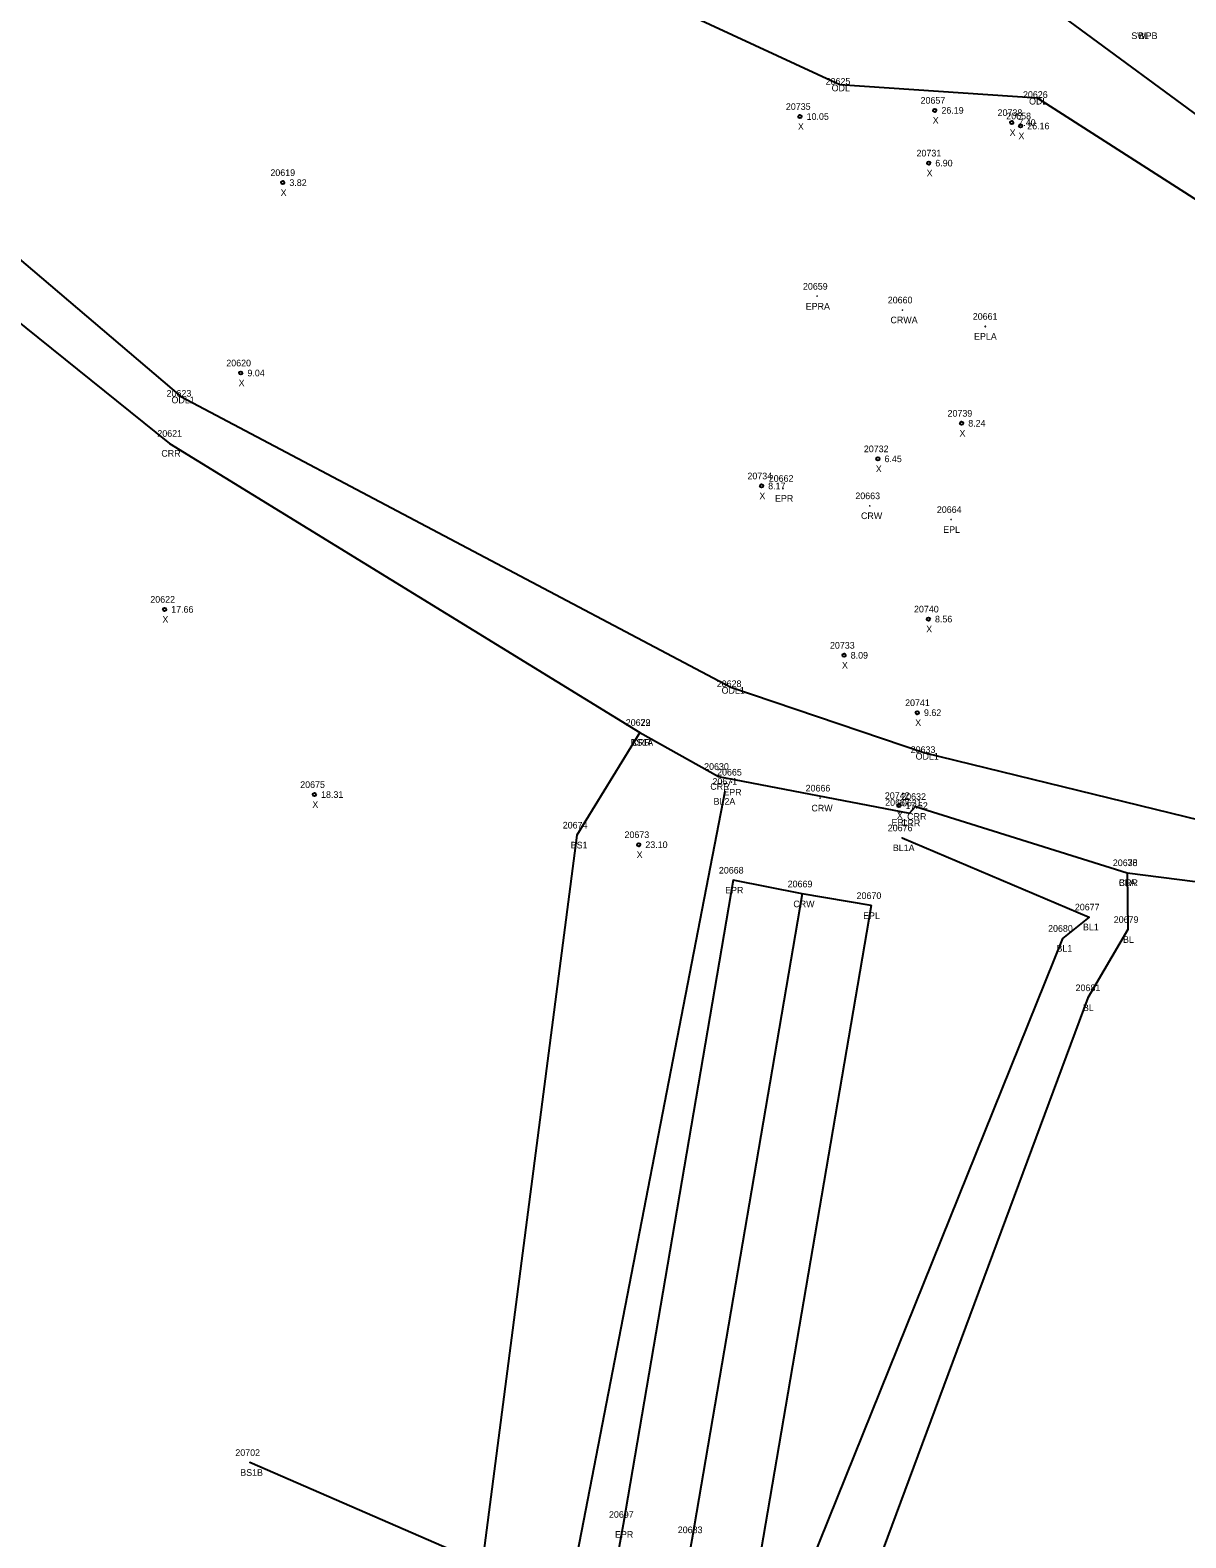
# Model space of a CAD drawing. Extents: x 2432729 to 2433340, y 684958 to 688103.
# Drawn here: x 2432998.9 to 2433172.9, y 685835 to 686061.9 of the extents above; entities that cross this region are included whole.
import ezdxf

# ---------------------------------------------------------------- set-up
doc = ezdxf.new("R2010")
doc.units = 0
for name, color, linetype in [('Default', 7, 'Continuous'), ('RD_DTM_BkLn1', 7, 'Continuous'), ('RD_DTM_BkLn2', 7, 'Continuous'), ('RD_EX_H2O', 7, 'Continuous'), ('RD_EX_H2O_txCode', 7, 'Continuous'), ('RD_EX_Road', 7, 'Continuous'), ('RD_EX_Road_txCode', 7, 'Continuous'), ('RD_Sketch8', 7, 'Continuous'), ('RD_SMD_Locator', 7, 'Continuous'), ('RD_SMD_Misc', 7, 'Continuous')]:
    doc.layers.add(name, color=color, linetype=linetype)

msp = doc.modelspace()

# ---------------------------------------------------------------- linework, layer by layer
at = {"layer": 'Default'}
for centre, radius in [((2433135.14, 686049.82), 0.25), ((2433148.06, 686047.47), 0.25), ((2433117.43, 686021.83), 0.001), ((2433130.27, 686019.77), 0.001), ((2433142.75, 686017.3), 0.001), ((2433112.31, 685992.92), 0.001), ((2433125.35, 685990.3), 0.001), ((2433137.62, 685988.23), 0.001), ((2433104.52, 685948.7), 0.001), ((2433117.88, 685946.3), 0.001), ((2433129.83, 685944.15), 0.001)]:
    msp.add_circle(centre, radius, dxfattribs=at)
at = {"layer": 'RD_DTM_BkLn1'}
for points in [[(2433103.52, 685947.31), (2433081.29, 685832.59), (2433076.2, 685788.7), (2433066.28, 685743.12), (2433052.78, 685695.75)], [(2433130.23, 685940.32), (2433158.37, 685928.4), (2433154.38, 685925.19), (2433116.47, 685831.2), (2433106.22, 685783.93), (2433096.24, 685736.13), (2433087.86, 685684.95)], [(2433125.56, 685930.12), (2433115.16, 685931.88), (2433104.8, 685933.95)], [(2433164.1, 685935.07), (2433164.23, 685926.52), (2433158.2, 685916.25), (2433126.08, 685829.8), (2433121.08, 685793.04)], [(2433115.16, 685931.88), (2433098.58, 685834.67), (2433089.77, 685786.77), (2433079.97, 685740.68), (2433067.41, 685690.62)]]:
    msp.add_lwpolyline(points, dxfattribs=at)
at = {"layer": 'RD_DTM_BkLn2'}
msp.add_lwpolyline([(2433090.75, 685956.18), (2433081.26, 685940.73), (2433067.01, 685831.1), (2433031.98, 685846.3)], dxfattribs=at)
at = {"layer": 'RD_EX_H2O'}
for points in [[(2432998.81, 686208.98), (2432991.26, 686158.53), (2433015.01, 686119.83), (2433043.41, 686089.59), (2433120.85, 686053.69), (2433150.58, 686051.7), (2433203.32, 686017.95), (2433331.51, 685987.84)], [(2433007.74, 686209.38), (2433001.59, 686166.41), (2433024.46, 686126.62), (2433051.58, 686097.06), (2433120.95, 686072.12), (2433152.82, 686065.09), (2433205.51, 686026.38), (2433335.15, 685993.61)], [(2432923.79, 686090.04), (2433021.62, 686006.73), (2433104.45, 685963.02), (2433133.66, 685953.1), (2433209.77, 685934.52), (2433322.81, 685903.72)], [(2432923.04, 686077.65), (2433019.93, 685999.69), (2433090.75, 685956.18), (2433102.59, 685949.56), (2433131.31, 685944.06), (2433132.23, 685945.04), (2433164.1, 685935.07), (2433204.66, 685929.9), (2433314.75, 685896.03)]]:
    msp.add_lwpolyline(points, dxfattribs=at)
at = {"layer": 'RD_EX_Road'}
for points in [[(2433104.8, 685933.95), (2433088.22, 685836.98), (2433079.44, 685788.63), (2433069.66, 685742.53), (2433057.55, 685694.23)], [(2433125.56, 685930.12), (2433108.96, 685832.94), (2433099.86, 685784.62), (2433089.82, 685738.23), (2433077.66, 685687.92)]]:
    msp.add_lwpolyline(points, dxfattribs=at)
at = {"layer": 'RD_SMD_Locator'}
for centre, radius in [((2433120.85, 686053.69), 0.001), ((2433150.58, 686051.7), 0.001), ((2433114.84, 686048.89), 0.25), ((2433146.72, 686047.97), 0.25), ((2433134.22, 686041.88), 0.25), ((2433036.96, 686038.94), 0.25), ((2433030.64, 686010.29), 0.25), ((2433021.62, 686006.73), 0.001), ((2433139.18, 686002.72), 0.25), ((2433019.93, 685999.69), 0.001), ((2433126.57, 685997.37), 0.25), ((2433109.05, 685993.29), 0.25), ((2433019.16, 685974.71), 0.25), ((2433134.17, 685973.25), 0.25), ((2433121.48, 685967.8), 0.25), ((2433104.45, 685963.02), 0.001), ((2433132.51, 685959.16), 0.25), ((2433090.75, 685956.18), 0.001), ((2433090.75, 685956.18), 0.001), ((2433133.66, 685953.1), 0.001), ((2433102.59, 685949.56), 0.001), ((2433041.73, 685946.84), 0.25), ((2433103.52, 685947.31), 0.001), ((2433129.74, 685945.18), 0.25), ((2433131.31, 685944.06), 0.001), ((2433132.23, 685945.04), 0.001), ((2433081.26, 685940.73), 0.001), ((2433090.56, 685939.29), 0.25), ((2433130.23, 685940.32), 0.001), ((2433104.8, 685933.95), 0.001), ((2433164.1, 685935.07), 0.001), ((2433164.1, 685935.07), 0.001), ((2433115.16, 685931.88), 0.001), ((2433125.56, 685930.12), 0.001), ((2433158.37, 685928.4), 0.001), ((2433154.38, 685925.19), 0.001), ((2433164.23, 685926.52), 0.001), ((2433158.2, 685916.25), 0.001), ((2433031.98, 685846.3), 0.001), ((2433088.22, 685836.98), 0.001)]:
    msp.add_circle(centre, radius, dxfattribs=at)

# ---------------------------------------------------------------- texts
at = {"layer": 'RD_EX_H2O_txCode'}
for s, p in [('SWPB', (2433164.74, 686060.55)), ('20625', (2433118.71, 686053.69)), ('ODL', (2433119.61, 686052.69)), ('20626', (2433148.42, 686051.7)), ('ODL', (2433149.34, 686050.7)), ('20623', (2433019.47, 686006.73)), ('ODL1', (2433020.21, 686005.73)), ('20621', (2433018.08, 686000.69)), ('CRR', (2433018.68, 685997.69)), ('20628', (2433102.31, 685963.02)), ('ODL1', (2433103.04, 685962.02)), ('20629', (2433088.61, 685957.18)), ('CRR', (2433089.5, 685954.18)), ('20633', (2433131.51, 685953.1)), ('ODL1', (2433132.25, 685952.1)), ('20630', (2433100.41, 685950.56)), ('CRR', (2433101.34, 685947.56)), ('20631', (2433129.45, 685945.06)), ('20632', (2433130.09, 685946.04)), ('CRR', (2433130.06, 685942.06)), ('CRR', (2433130.98, 685943.04)), ('20635', (2433161.95, 685936.07)), ('CRR', (2433162.84, 685933.07))]:
    msp.add_text(s, height=1, dxfattribs=at).set_placement(p)
at = {"layer": 'RD_EX_Road_txCode'}
for s, p in [('20659', (2433115.29, 686022.83)), ('EPRA', (2433115.71, 686019.83)), ('20661', (2433140.86, 686018.3)), ('EPLA', (2433141.05, 686015.3)), ('20662', (2433110.14, 685993.92)), ('EPR', (2433111.08, 685990.92)), ('20664', (2433135.45, 685989.23)), ('EPL', (2433136.41, 685986.23)), ('20665', (2433102.36, 685949.7)), ('EPR', (2433103.3, 685946.7)), ('20667', (2433127.67, 685945.15)), ('EPL', (2433128.63, 685942.15)), ('20668', (2433102.63, 685934.95)), ('EPR', (2433103.57, 685931.95)), ('20670', (2433123.37, 685931.12)), ('EPL', (2433124.35, 685928.12)), ('20697', (2433086.08, 685837.98)), ('EPR', (2433086.99, 685834.98))]:
    msp.add_text(s, height=1, dxfattribs=at).set_placement(p)
at = {"layer": 'RD_Sketch8'}
for s, p in [('20735', (2433112.72, 686049.89)), ('20657', (2433133, 686050.82)), ('26.19', (2433136.14, 686049.32)), ('20738', (2433144.6, 686048.97)), ('X', (2433114.53, 686046.89)), ('10.05', (2433115.84, 686048.39)), ('X', (2433134.83, 686047.82)), ('20658', (2433145.91, 686048.47)), ('7.40', (2433147.72, 686047.47)), ('26.16', (2433149.06, 686046.97)), ('X', (2433146.41, 686045.97)), ('X', (2433147.74, 686045.47)), ('20731', (2433132.39, 686042.88)), ('20619', (2433035.1, 686039.94)), ('X', (2433133.91, 686039.88)), ('6.90', (2433135.22, 686041.38)), ('3.82', (2433037.96, 686038.44)), ('X', (2433036.64, 686036.94)), ('20620', (2433028.46, 686011.29)), ('X', (2433030.32, 686008.29)), ('9.04', (2433031.64, 686009.79)), ('20739', (2433137.06, 686003.72)), ('8.24', (2433140.18, 686002.22)), ('X', (2433138.86, 686000.72)), ('20732', (2433124.46, 685998.37)), ('6.45', (2433127.57, 685996.87)), ('20734', (2433106.93, 685994.29)), ('X', (2433126.26, 685995.37)), ('8.17', (2433110.05, 685992.79)), ('X', (2433108.73, 685991.29)), ('20622', (2433017.02, 685975.71)), ('17.66', (2433020.16, 685974.21)), ('20740', (2433132.01, 685974.25)), ('X', (2433018.84, 685972.71)), ('8.56', (2433135.17, 685972.75)), ('X', (2433133.85, 685971.25)), ('20733', (2433119.36, 685968.8)), ('8.09', (2433122.48, 685967.3)), ('X', (2433121.16, 685965.8)), ('20741', (2433130.67, 685960.16)), ('9.62', (2433133.51, 685958.66)), ('X', (2433132.19, 685957.16)), ('20675', (2433039.59, 685947.84)), ('X', (2433041.42, 685944.84)), ('18.31', (2433042.73, 685946.34)), ('20742', (2433127.62, 685946.18)), ('17.52', (2433130.74, 685944.68)), ('X', (2433129.43, 685943.18)), ('20673', (2433088.42, 685940.29)), ('23.10', (2433091.56, 685938.79)), ('X', (2433090.25, 685937.29))]:
    msp.add_text(s, height=1, dxfattribs=at).set_placement(p)
at = {"layer": 'RD_SMD_Misc'}
for s, p in [('BL', (2433165.77, 686060.55)), ('20660', (2433128.06, 686020.77)), ('CRWA', (2433128.47, 686017.77)), ('20663', (2433123.18, 685991.3)), ('CRW', (2433124.03, 685988.3)), ('20672', (2433088.61, 685957.18)), ('BS1A', (2433089.32, 685954.18)), ('20671', (2433101.66, 685948.31)), ('20666', (2433115.69, 685947.3)), ('BL2A', (2433101.83, 685945.31)), ('CRW', (2433116.56, 685944.3)), ('20674', (2433079.12, 685941.73)), ('20676', (2433128.06, 685941.32)), ('BS1', (2433080.32, 685938.73)), ('BL1A', (2433128.82, 685938.32)), ('20678', (2433161.95, 685936.07)), ('BLA', (2433162.85, 685933.07)), ('20669', (2433112.99, 685932.88)), ('CRW', (2433113.84, 685929.88)), ('20677', (2433156.23, 685929.4)), ('20680', (2433152.2, 685926.19)), ('BL1', (2433157.45, 685926.4)), ('20679', (2433162.09, 685927.52)), ('BL', (2433163.48, 685924.52)), ('BL1', (2433153.46, 685923.19)), ('20681', (2433156.34, 685917.25)), ('BL', (2433157.44, 685914.25)), ('20702', (2433029.82, 685847.3)), ('BS1B', (2433030.56, 685844.3)), ('20683', (2433096.44, 685835.67))]:
    msp.add_text(s, height=1, dxfattribs=at).set_placement(p)

doc.saveas('drawing.dxf')
